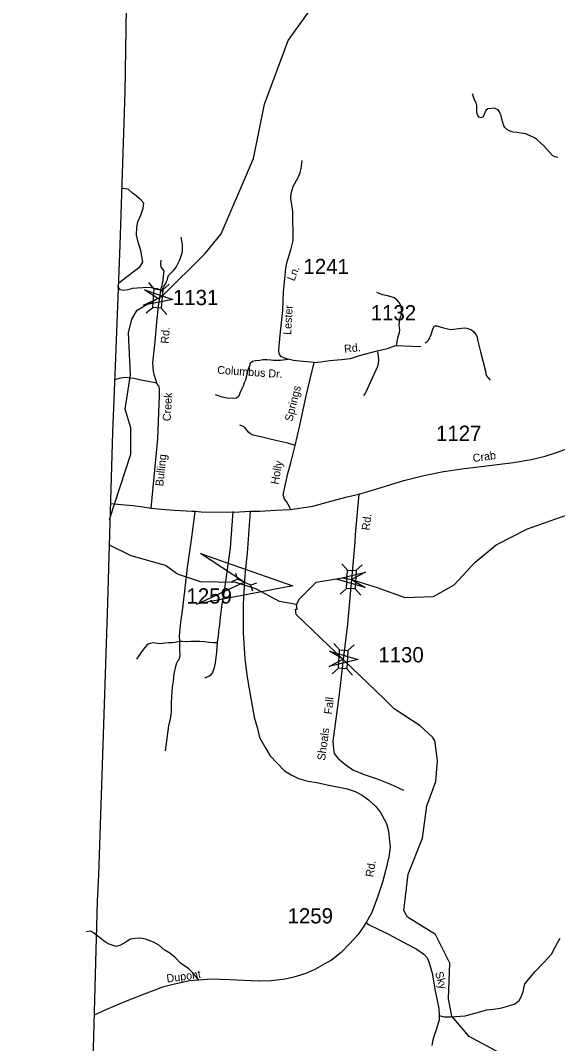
# Model space of a CAD drawing. Extents: x 884530 to 1028605, y 526725 to 653634.
# Drawn here: x 923339 to 927736, y 556470 to 564854 of the extents above; entities that cross this region are included whole.
import ezdxf

# ---------------------------------------------------------------- set-up
doc = ezdxf.new("R2010")
doc.units = 0
for name, color, linetype in [('Exist Boundary Political CountyLine', 7, 'Continuous'), ('Exist Hydrographic Creek Single Shore', 7, 'Continuous'), ('Exist Road Non-System Type 51', 7, 'Continuous'), ('Exist Road Non-System Type 51 Label', 7, 'Continuous'), ('Exist Road Secondary Structure Culvert Attributed CELL', 7, 'Continuous'), ('Exist Road Secondary Structure Culvert CELL', 7, 'Continuous'), ('Exist Road Secondary Structure Standard Bridge Attributed CELL', 7, 'Continuous'), ('Exist Road Secondary Structure Standard Bridge CELL', 7, 'Continuous'), ('Exist Road Secondary Type 41 Attributed', 7, 'Continuous'), ('Exist Road Secondary Type 51 Attributed', 7, 'Continuous'), ('Exist Road Secondary Type 51 Label', 7, 'Continuous'), ('Exist Road Secondary Type 51 Number Label', 7, 'Continuous')]:
    doc.layers.add(name, color=color, linetype=linetype)

msp = doc.modelspace()

# ---------------------------------------------------------------- linework, layer by layer
at = {"layer": 'Exist Boundary Political CountyLine'}
msp.add_lwpolyline([(923046.9, 569272.4), (924302.7, 568698.5), (924298.8, 568505.6), (924287.9, 568293.2), (924212.8, 565487.4), (924193.2, 564269.3), (924152, 563011.9), (924114.4, 562020.6), (924093, 561477.1), (924049.7, 559995.6), (924009.2, 558754.2), (923976.8, 557852.8), (923967.1, 557636.9), (923923.3, 556025.5)], dxfattribs=at)
at = {"layer": 'Exist Hydrographic Creek Single Shore'}
for points in [[(924067.9, 560764.1), (924242.7, 561299.7), (924242.2, 561516.3), (924197.6, 561668.1), (924241.1, 561949.5), (924223.1, 562294.2), (924250, 562405.8), (924295.4, 562480.2), (924342.2, 562506.8), (924500.1, 562595.8), (924852.3, 562944.7), (924983.1, 563106.1), (925247, 563724.3), (925338.2, 564168.8), (925531.8, 564689.9), (925768.9, 565023.2), (925846.6, 565093.8), (925900.9, 565210.8), (925850.2, 565428.4)], [(925599.7, 560068.1), (925623, 560115.1), (925760.3, 560250.2), (925976.4, 560287.6), (926046.4, 560274.2), (926259.6, 560206.9), (926485.6, 560125.7), (926719.4, 560134.1), (926889.4, 560229.1), (927063, 560416), (927234.9, 560556.9), (927489.8, 560689.6), (928418.7, 561015.5), (928772, 561103.5), (928883, 561173.5), (929039.2, 561344.2)], [(925599.7, 560068.1), (925459.3, 560092.1), (925267.2, 560196.3), (925101.8, 560249.7), (924813.9, 560254.5), (924624.5, 560317.4), (924527, 560388.2), (924246.3, 560466.1), (924061.9, 560556.4)], [(927412.9, 556311.3), (927012.8, 556527.8), (926871.1, 556695.2), (926842.8, 556836.9), (926853.4, 557128.7), (926736.7, 557364.1), (926508.5, 557506.5), (926476.9, 557559.7), (926512.7, 557857.6), (926631.6, 558153.8), (926666.1, 558418.9), (926740.1, 558617.5), (926754.6, 558791.2), (926730.4, 558954.1), (926712.5, 558981.8), (926611.8, 559072.8), (926397.5, 559212.5), (926317.3, 559294.9), (925597, 559986.7), (925592.2, 560030.6), (925603.6, 560030.8), (925599.7, 560068.1)]]:
    msp.add_lwpolyline(points, dxfattribs=at)
at = {"layer": 'Exist Road Non-System Type 51'}
for points in [[(927739.8, 563731.3), (927728, 563732.9), (927715, 563737.2), (927696.1, 563747.9), (927622.9, 563826.9), (927566.3, 563877.7), (927541.5, 563895.4), (927499.1, 563914.3), (927475.5, 563924.9), (927437.7, 563931.9), (927403.4, 563935.5), (927372.8, 563940.2), (927339.6, 563950.8), (927322, 563960.2), (927305.4, 563976.4), (927296.3, 563990.1), (927280.7, 564046.5), (927274.8, 564074.8), (927267.8, 564092.4), (927260.6, 564106.6), (927248.9, 564120.7), (927237.4, 564128.6), (927221, 564135.4), (927166.4, 564131.2), (927149.8, 564116.1), (927130.8, 564072.4), (927121.4, 564061.7), (927108.4, 564055.9), (927094.3, 564063), (927082.4, 564075.9), (927075.3, 564098.3), (927075.3, 564124.3), (927074.2, 564158.5), (927070.7, 564179.7), (927057.7, 564204.5), (927040, 564254.1)], [(925551.6, 562975.7), (925570.6, 563050.5), (925569.7, 563288.6), (925553.4, 563399), (925555, 563439.6), (925570.9, 563493), (925616.8, 563578.6), (925628.5, 563607.6), (925637.4, 563640.5), (925646.1, 563707)], [(924495.2, 562637.4), (924462.2, 562655.1), (924437.7, 562655.1), (924405.1, 562667.3), (924340, 562663.4), (924294.7, 562661.3), (924257.5, 562659.2), (924218.3, 562646.9), (924183.3, 562640.7), (924158.5, 562646.9), (924137.9, 562669.6), (924144.1, 562704.6), (924319.4, 562838.6), (924340, 562873.8), (924325.6, 562968.8), (924302.9, 563036.8), (924288.5, 563096.7), (924290.9, 563156.9), (924300.9, 563203.9), (924323.5, 563259.7), (924344.1, 563315.4), (924350.4, 563356.6), (924327.7, 563381.4), (924286.4, 563418.6), (924257.6, 563439.2), (924220.4, 563472.2), (924167.2, 563476.3)], [(924551.3, 562763.1), (924561.9, 562776.4), (924575.8, 562789.2), (924591.4, 562804.5), (924607.8, 562824.1), (924619.8, 562842.4), (924631.1, 562865), (924640.9, 562887.4), (924649.2, 562907.1), (924656, 562925.9), (924660.8, 562942.5), (924664.4, 562960.5), (924666, 562980.8), (924664.5, 563016.4), (924659.8, 563048.1), (924653.6, 563077.9)], [(924495.2, 562637.4), (924512.5, 562674.6), (924521.5, 562688.2), (924528.8, 562700), (924535.8, 562714.7), (924541.7, 562733), (924545.9, 562749.3), (924551.3, 562763.1)], [(926417.8, 562190.3), (926426.2, 562237.9), (926429.7, 562254.5), (926434.2, 562271.7), (926442.8, 562297.3), (926445.7, 562316.9), (926442.7, 562336.5), (926439.7, 562362.2), (926441.2, 562380.3), (926445.7, 562401.4), (926448.8, 562419.5), (926454.8, 562436.1), (926462.3, 562463.2), (926459.4, 562491.9), (926453.3, 562519.1), (926439.7, 562543.2), (926423.2, 562562.8), (926397.5, 562580.9), (926373.3, 562588.4), (926343.2, 562597.5), (926302.5, 562606.6), (926257.2, 562626.2)], [(926653.6, 562211.7), (926665.8, 562219.9), (926681.7, 562238), (926702.1, 562280.6), (926717.9, 562333.6), (926728.5, 562352), (926748.6, 562351.6), (926801.8, 562334.7), (926859.3, 562323.2), (926884.4, 562323.8), (926972.9, 562336.6), (926994.9, 562332.5), (927031.7, 562319.5), (927054.9, 562299.5), (927071.5, 562272.9), (927077.5, 562256.2), (927084, 562226.9), (927104.2, 562137.7), (927146, 561979.6), (927152.1, 561946.1), (927170.5, 561923.7), (927184.8, 561907.4)], [(925528, 562076.8), (925467.2, 562066.6), (925432.3, 562069.2), (925409.6, 562068.9), (925389.2, 562070.9), (925357.9, 562074.3), (925324.2, 562074.3), (925297.6, 562067.1), (925263.8, 562064.7), (925239.7, 562061), (925220.3, 562044.2), (925213.1, 562023.6), (925203.5, 561995.9), (925197.5, 561975.4), (925192.6, 561956.1), (925186.6, 561930.7), (925180.5, 561905.4), (925169.7, 561884.1), (925163, 561858.4), (925149.9, 561828.9), (925135.4, 561800.6), (925125.8, 561776.2), (925107.5, 561759.9), (925071, 561755.6), (925028, 561759.8), (924991.2, 561767.7), (924961.5, 561777), (924935.4, 561787)], [(926261.7, 562138.9), (926267.7, 562104.2), (926270.7, 562068), (926267.7, 562042.4), (926261.7, 562019.8), (926163.7, 561804), (926147.1, 561779.9)], [(924454.4, 561882.4), (924326.5, 561906.9), (924266.5, 561921.7), (924196.3, 561927.9), (924159.1, 561923.7), (924110, 561910.1)], [(925588.4, 561370.7), (925526.9, 561391.2), (925405, 561417.8), (925307.3, 561441.9), (925244.5, 561456.4), (925221.6, 561467.3), (925207.1, 561479.4), (925173.3, 561520.4), (925151.5, 561533.7), (925134.7, 561538.5)], [(924765.4, 560828.9), (924737.6, 560599.6), (924703.9, 560372.7), (924682.2, 560178.5), (924659.7, 559994), (924648.8, 559922.4), (924640.2, 559840.9), (924639.4, 559810.5), (924640.8, 559765.1)], [(925076.8, 560830.1), (925056.3, 560533.2), (925003.2, 560159.1), (924988.1, 560070.4), (924974.5, 559960.7), (924967.9, 559902.9), (924961.4, 559852.4), (924957.9, 559806.2), (924952.7, 559779.5), (924949.9, 559753.5)], [(924640.8, 559765.1), (924615.9, 559760.7), (924602.4, 559756.5), (924580.3, 559753.1), (924550.5, 559753.1), (924520, 559751.3), (924489.4, 559747.1), (924462, 559747.5), (924426.7, 559754.8), (924401.1, 559749.6), (924383.3, 559744.6), (924369.7, 559733.5), (924346, 559702.9), (924324.7, 559672.4), (924307.7, 559648.5), (924290.1, 559621.6)], [(924640.8, 559765.1), (924641.7, 559736.9), (924641.7, 559697.2), (924643.1, 559653.2), (924640.8, 559633.7), (924634.4, 559614.9), (924625.9, 559603.9), (924617.8, 559588.2), (924609.4, 559561), (924595.5, 559501.2), (924588.7, 559439.1), (924581, 559390.4), (924576.4, 559316.6), (924572.7, 559259.1), (924572.7, 559196.5), (924571.3, 559162.7), (924565.1, 559130.2), (924550.1, 559074), (924523.9, 558870.3)], [(924949.9, 559753.5), (924918.9, 559753.5), (924883.4, 559757.1), (924847.3, 559761.4), (924806.9, 559765.8), (924773, 559764.4), (924734, 559764.4), (924699.4, 559763.6), (924664.7, 559765.8), (924640.8, 559765.1)], [(924949.9, 559753.5), (924943.1, 559681.5), (924940.3, 559652.7), (924938.7, 559635.7), (924933.1, 559591.4), (924922.7, 559540.4), (924910.2, 559510.3), (924895.2, 559490.3), (924880.1, 559479.1), (924863.9, 559471.5), (924845.2, 559465.3)], [(924799.2, 556989.1), (924750.1, 557050), (924716.4, 557082.1), (924650.4, 557129.5), (924604.8, 557175.2), (924562.4, 557210.7), (924515, 557239.4), (924469.4, 557278.4), (924427.1, 557301.6), (924362, 557324.9), (924323.8, 557334.2), (924278.2, 557332.5), (924241, 557325.8), (924212.3, 557308.8), (924186.9, 557291.9), (924151.3, 557273.3), (924122.6, 557266.5), (924088.7, 557276.7), (924056.7, 557288.5), (924024.5, 557308.8), (923997.4, 557330.8), (923960.2, 557357.9), (923939.9, 557374.8), (923914.4, 557390), (923880.6, 557386.6)], [(926766.5, 556701.2), (926806.7, 556689.1), (926862.8, 556690.5), (926978.7, 556696.9), (927090.3, 556728.9), (927157.8, 556747.3), (927211.6, 556751.9), (927279.8, 556762.7), (927337.3, 556780.1), (927386.7, 556796.1), (927421.5, 556824.1), (927437.6, 556852.2), (927455, 556896.3), (927469.3, 556959.9), (927553.8, 557060.7), (927623.3, 557135.6), (927690.1, 557205), (927710.2, 557251.9), (927758.4, 557333.4)]]:
    msp.add_lwpolyline(points, dxfattribs=at)
at = {"layer": 'Exist Road Secondary Structure Culvert Attributed CELL'}
msp.add_lwpolyline([(924814.4, 560485), (925569.7, 560221.5), (924783.8, 560072.1), (925170.8, 560251)], close=True, dxfattribs=at)
at = {"layer": 'Exist Road Secondary Structure Culvert CELL'}
for p, q in [((925099.9, 560324.8), (925116, 560276.6)), ((925068.8, 560257.9), (925116, 560276.6)), ((925225.6, 560225.5), (925116, 560276.6)), ((925272.8, 560244.1), (925225.6, 560225.5)), ((925241.7, 560177.3), (925225.6, 560225.5))]:
    msp.add_line(p, q, dxfattribs=at)
at = {"layer": 'Exist Road Secondary Structure Standard Bridge Attributed CELL'}
for points in [[(924355.5, 562647.7), (924585.7, 562567.3), (924346.1, 562521.8), (924464.1, 562576.3)], [(926160.9, 560208.4), (925926.9, 560277.1), (926163.9, 560334.6), (926048.8, 560274.2)], [(925869.9, 559685.5), (926103.9, 559616.8), (925866.9, 559559.3), (925982, 559619.7)]]:
    msp.add_lwpolyline(points, close=True, dxfattribs=at)
at = {"layer": 'Exist Road Secondary Structure Standard Bridge CELL'}
for p, q in [((924435, 562653.9), (924390.7, 562706.7)), ((924503.8, 562647.8), (924556.6, 562692.2)), ((924368.7, 562459), (924421.5, 562503.4)), ((924536.2, 562444.3), (924491.8, 562497.2)), ((926017, 560350.7), (925970.9, 560401.9)), ((926085.9, 560347.1), (926137.2, 560393.2)), ((925957.5, 560153.6), (926008.8, 560199.8)), ((926125.4, 560144.8), (926079.3, 560196.1)), ((925950.2, 559696.2), (925904, 559747.5)), ((926019.1, 559692.6), (926070.4, 559738.7)), ((925890.7, 559499.1), (925942, 559545.3)), ((926058.6, 559490.3), (926012.5, 559541.6))]:
    msp.add_line(p, q, dxfattribs=at)
for points in [[(924421.5, 562503.4), (924434.7, 562653.9), (924505, 562647.7), (924491.8, 562497.2)], [(926008.8, 560199.8), (926016.7, 560350.7), (926087.2, 560347), (926079.3, 560196.1)], [(925942, 559545.3), (925949.9, 559696.2), (926020.4, 559692.5), (926012.5, 559541.6)]]:
    msp.add_lwpolyline(points, close=True, dxfattribs=at)
at = {"layer": 'Exist Road Secondary Type 41 Attributed'}
for points in [[(926108.4, 560973.2), (926078.2, 560641.3), (926075.9, 560579.4), (926049, 560272.2)], [(926049, 560272.2), (926038.8, 560156.4), (926016, 559907), (925982.3, 559616.7)], [(925982.3, 559616.7), (925949.2, 559333), (925897.4, 558948.6), (925901.1, 558884.5), (925907.7, 558846.1), (925938.4, 558809.1), (925994.8, 558761), (926059.1, 558714.7), (926153.6, 558675.3), (926258.9, 558640.2), (926367.5, 558595.1), (926474.5, 558546.6)]]:
    msp.add_lwpolyline(points, dxfattribs=at)
at = {"layer": 'Exist Road Secondary Type 51 Attributed'}
for points in [[(925742.4, 562050.9), (925654.9, 562059.4), (925622.7, 562061.7), (925574.2, 562067.1), (925509.7, 562083.2), (925477.2, 562099.2), (925459.6, 562117.6), (925455.4, 562145.1), (925457.2, 562188.2), (925469.3, 562303.8), (925486.1, 562478.7), (925493.5, 562629.4), (925499.6, 562708.8), (925506.3, 562767.9), (925513, 562823.1), (925519.8, 562868.9), (925551.6, 562975.7)], [(924480.6, 562584.3), (924487.8, 562638.5), (924493.2, 562667.7), (924498.9, 562682.9), (924502.3, 562704.4), (924508.3, 562722.2), (924506.6, 562740.7), (924514.6, 562800.7), (924491.9, 562835.6), (924488.8, 562857.9), (924489.9, 562889.3)], [(924407.9, 560858.9), (924434.3, 561111.4), (924464.3, 561424.7), (924478.5, 561784.2), (924476.2, 561837.5), (924470.8, 561859.8), (924455.6, 561880.3), (924446.1, 561908.6), (924434, 561952.9), (924433.7, 561956.2), (924427.3, 561977.7), (924422.6, 562047.9), (924442.8, 562222.8), (924454.9, 562382.9), (924470.3, 562512), (924480.6, 562584.3)], [(925742.4, 562050.9), (925797.2, 562057.4), (925868.4, 562067.9), (925968.1, 562077), (926040.1, 562085.6), (926113.7, 562110.1), (926259.3, 562147.7), (926345, 562165.3), (926380, 562180.1), (926412.3, 562189.5), (926618.1, 562182.8)], [(925549, 560846.8), (925542.4, 560868.6), (925516.4, 560911.2), (925499.7, 560931.3), (925489.7, 560966.4), (925529.4, 561140.7), (925552.8, 561228.5), (925588.4, 561370.7), (925627.2, 561534.5), (925677.7, 561777.3), (925742.4, 562050.9)], [(926108.4, 560973.2), (926256.7, 561017), (926476.7, 561083.4), (926641.6, 561125.2), (926803.4, 561157.6), (926953.3, 561180.8), (927376.4, 561231.3), (927519.3, 561256), (927636.3, 561283.9), (927727.5, 561312.7), (927893.8, 561374.7)], [(925549, 560846.8), (925732.3, 560874.8), (925881.3, 560914.2), (926014, 560950.6), (926108.4, 560973.2)], [(924076, 560896.7), (924162.3, 560888.6), (924262.8, 560880.4), (924339.8, 560869.8), (924407.9, 560858.9)], [(924407.9, 560858.9), (924490.3, 560849), (924600.7, 560841.5), (924742.6, 560832.5), (924769, 560832.5), (924818.2, 560828.5), (925088.3, 560824.9), (925219.2, 560834)], [(925219.2, 560834), (925193.8, 560488.7), (925180.1, 560338.1), (925170.1, 560224.4), (925162.6, 560068.8), (925163.4, 559836.5), (925175.7, 559623.9), (925193.8, 559472.1), (925210.3, 559378.1), (925253.1, 559146.3), (925281.1, 559052.2), (925297.3, 558979), (925348, 558887.2), (925384.7, 558826.9), (925440.5, 558766.8), (925501, 558704.6), (925556.1, 558671.2), (925616.3, 558642.7), (925691.5, 558619.3), (925765, 558609.3), (925850.3, 558590.9), (925931.3, 558575), (926014.1, 558559.1), (926078.4, 558534.9), (926136.9, 558504.8), (926188.7, 558468), (926243.8, 558419.5), (926284, 558369.4), (926334.9, 558273.9), (926353.2, 558210.2), (926360.4, 558129.8), (926366.7, 558080.9), (926356.3, 558001.6), (926326.6, 557885.3), (926303.6, 557792.9), (926259.7, 557662.9), (926212.9, 557538.8), (926170, 557462)], [(925219.2, 560834), (925255.2, 560832.7), (925300.7, 560833.4), (925427.1, 560840.9), (925549, 560846.8)], [(926170, 557462), (926140.2, 557416.7), (926101.2, 557360.9), (926034.3, 557286.2), (925963.9, 557217.1), (925885.3, 557155), (925825.9, 557119.7), (925750.1, 557077.7), (925676, 557043.8), (925577.9, 557014.8), (925507.1, 556997.4), (925390.6, 556985.5), (925296.5, 556980.8), (925290.5, 556981.1), (925165.3, 556986.9), (925053, 556992.3), (924900.6, 556997.7), (924799.2, 556989.1), (924723.2, 556984), (924578.1, 556952.6), (924500.8, 556931.1), (924437.9, 556906.9), (924365.9, 556881.3), (924199.8, 556814), (924044.4, 556748.1), (923941.7, 556703.5)], [(926170, 557462), (926193.4, 557443.2), (926351.4, 557365.6), (926506.1, 557283.7), (926569, 557252.6), (926579.4, 557246.8)], [(926579.4, 557246.8), (926642.5, 557201.7), (926668.4, 557174.2), (926682.8, 557140.4), (926709.2, 557048), (926734.8, 556901.8), (926750.7, 556823.7), (926764.8, 556756.3), (926766.5, 556701.2), (926766.1, 556663.9), (926763.7, 556656), (926744, 556589.9), (926724.7, 556528.9), (926712.6, 556487.5), (926707.6, 556454.9)]]:
    msp.add_lwpolyline(points, dxfattribs=at)

# ---------------------------------------------------------------- texts
at = {"layer": 'Exist Road Non-System Type 51 Label'}
msp.add_text('Columbus Dr.', height=65.617, rotation=356.18291, dxfattribs=at).set_placement((924948.4, 561959.1))
at = {"layer": 'Exist Road Secondary Type 51 Label'}
for s, rotation, p in [('Ln.', 67.67189, (925580.2, 562713.7)), ('Lester', 86.91514, (925555.3, 562276.7)), ('Rd.', 85.9286, (924552.3, 562204)), ('Rd.', 6.42691, (925992.3, 562129.8)), ('Springs', 76.09533, (925564.6, 561563.6)), ('Creek', 86.93234, (924568.6, 561569.5)), ('Crab', 7.98109, (927046.8, 561234.8)), ('Bulling', 84.05824, (924508, 561034.9)), ('Holly', 79.66643, (925450.8, 561048.2)), ('Rd.', 83.5264, (926197.4, 560673.1)), ('Fall', 83.39444, (925889.3, 559165.4)), ('Shoals', 82.33027, (925832.6, 558787.1)), ('Rd.', 81.37892, (926227.7, 557831)), ('Dupont', 7.67171, (924539.3, 556970.3)), ('Sky', 285.30525, (926733, 557051.6))]:
    msp.add_text(s, height=65.62, rotation=rotation, dxfattribs=at).set_placement(p)
at = {"layer": 'Exist Road Secondary Type 51 Number Label'}
for s, p in [('1241', (925656.1, 562775.7)), ('1131', (924587.1, 562521.5)), ('1132', (926207, 562396.5)), ('1127', (926741.4, 561408.8)), ('1259', (924698.3, 560076)), ('1130', (926269.1, 559594.2)), ('1259', (925526, 557454.7))]:
    msp.add_text(s, height=125, dxfattribs=at).set_placement(p)

doc.saveas('drawing.dxf')
